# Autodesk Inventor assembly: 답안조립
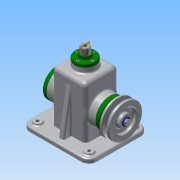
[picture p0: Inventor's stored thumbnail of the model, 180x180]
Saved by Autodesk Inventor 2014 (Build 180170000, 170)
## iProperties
Created: 2015-12
Part Number: 답안조립
Document SubType Name: Assembly
Designer: Administrator
Author: Administrator
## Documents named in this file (19)
- D:\451225V1020\답안조립.iam
- D:\451225V1020\베어링 15 x 35 x 11.ipt
- D:\451225V1020\볼트 M3 x 8.ipt
- D:\451225V1020\볼트 M4 x 10.ipt
- D:\451225V1020\볼트 M6 x 12.ipt
- D:\451225V1020\상부부시.ipt
- D:\451225V1020\슬라이드바.ipt
- D:\451225V1020\앞커버.ipt
- D:\451225V1020\오일실 15 25 7.ipt
- D:\451225V1020\와셔.ipt
- D:\451225V1020\키 5 x 5 x 14.ipt
- D:\451225V1020\편심축.ipt
- D:\451225V1020\V-벨트풀리.ipt
- D:\451225V1020\1-본체.ipt
- D:\451225V1020\고정핀.ipt
- D:\451225V1020\뒤커버.ipt
- D:\451225V1020\링크.ipt
- D:\451225V1020\멈춤링 6 x 5.ipt
- D:\451225V1020\멈춤링 15 x 1.ipt
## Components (16 placed, 6 different names)
1. ISO 4018 M6 x 12:1
2. V-벨트풀리:1
3. 1-본체:1
4. 고정핀:1
5. ISO 4762 M4 x 10:2
6. ISO 4762 M4 x 10:3
7. ISO 4762 M4 x 10:4
8. ISO 4762 M4 x 10:5
9. ISO 4762 M4 x 10:1
10. ISO 4762 M4 x 10:6
11. ISO 4762 M4 x 10:7
12. ISO 4762 M4 x 10:8
13. ISO 4762 M3 x 8:1
14. ISO 4762 M3 x 8:2
15. ISO 4762 M3 x 8:3
16. ISO 4762 M3 x 8:4
